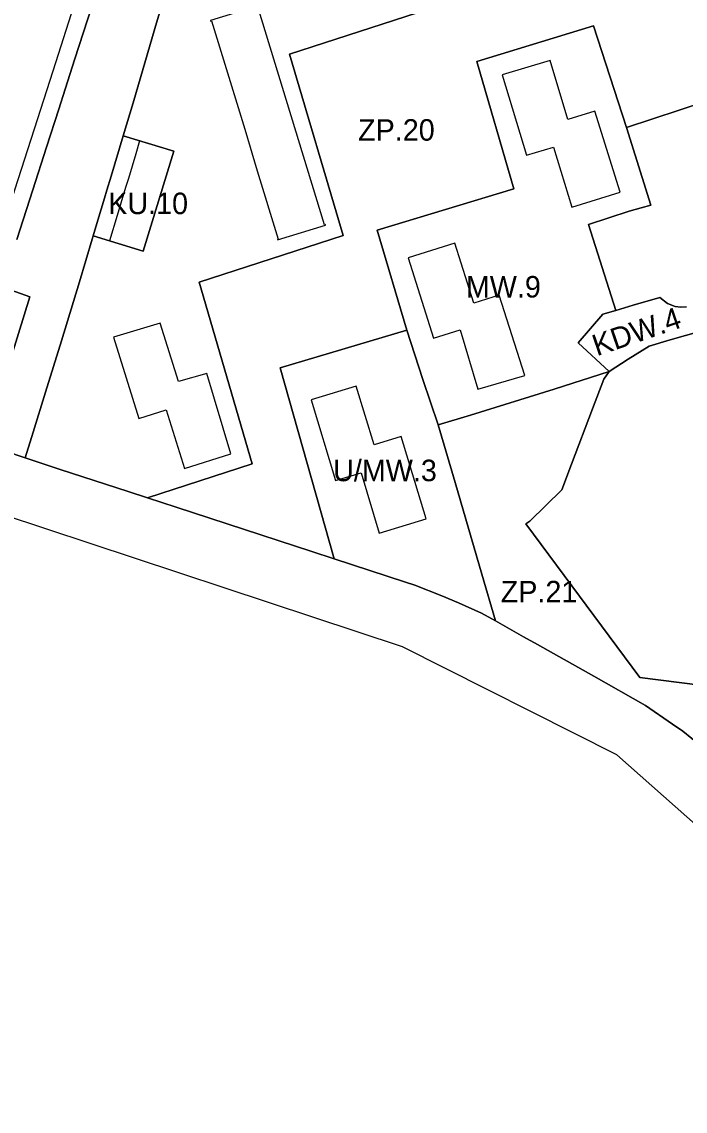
# Model space of a CAD drawing. Extents: x 7429178 to 7430831, y 5550228 to 5551611.
# Drawn here: x 7430171.5 to 7430325.9, y 5550756.2 to 5551009.6 of the extents above; entities that cross this region are included whole.
import ezdxf

# ---------------------------------------------------------------- set-up
doc = ezdxf.new("R2010")
doc.units = 0
for name, color, linetype in [('linie rozgraniczające', 7, 'Continuous'), ('nieprzekraczalne linie zabudowy', 7, 'Continuous'), ('obowiazujace linie zabudowy', 7, 'Continuous'), ('przeznaczenia terenów', 7, 'Continuous')]:
    doc.layers.add(name, color=color, linetype=linetype)

msp = doc.modelspace()

# ---------------------------------------------------------------- linework, layer by layer
at = {"layer": 'linie rozgraniczające'}
for points in [[(7430170.65, 5551043.22), (7430177.48, 5551062.44), (7430199.45, 5551057.06), (7430199.45, 5551057.06), (7430199.42, 5551056.95), (7430199.42, 5551056.95), (7430199.35, 5551056.75), (7430199.26, 5551056.46), (7430199.31, 5551056.2), (7430199.96, 5551050.84), (7430199.96, 5551050.84), (7430198.56, 5551046.5), (7430195.75, 5551037.8), (7430192.64, 5551028.18), (7430187.78, 5551013.14), (7430183.84, 5551000.93), (7430181.57, 5550993.91), (7430180.06, 5550989.22), (7430177.24, 5550980.42), (7430174.04, 5550970.46), (7430170.35, 5550958.95)], [(7430205.83, 5551019.51), (7430202.46, 5551008.03), (7430197.37, 5550990.71), (7430195.07, 5550983.04), (7430192.26, 5550973.68), (7430191.28, 5550970.4), (7430190.71, 5550968.51), (7430189.18, 5550963.43), (7430188.08, 5550959.77), (7430187.84, 5550958.98), (7430184.88, 5550949.09), (7430180.7, 5550935.39), (7430177, 5550923.42), (7430174.12, 5550914.11), (7430172.28, 5550908.16), (7430162.79, 5550911.32)], [(7430271.64, 5551014.25), (7430233.79, 5551002.02), (7430246.24, 5550959.84), (7430212.78, 5550949.01), (7430225.12, 5550906.71), (7430200.69, 5550898.84), (7430196.19, 5550900.31), (7430180.41, 5550905.46), (7430172.28, 5550908.16), (7430174.12, 5550914.11), (7430177, 5550923.42), (7430180.7, 5550935.39), (7430184.88, 5550949.09), (7430187.84, 5550958.98), (7430188.08, 5550959.77), (7430199.73, 5550956.21), (7430206.83, 5550979.45), (7430195.07, 5550983.04), (7430197.37, 5550990.71), (7430202.46, 5551008.03), (7430205.83, 5551019.51)], [(7430348.95, 5550997.08), (7430312.19, 5550985), (7430304.56, 5551008.63), (7430277.37, 5551000.36), (7430285.99, 5550970.73), (7430254.2, 5550961.12), (7430261.07, 5550937.83), (7430231.57, 5550929.08), (7430244.2, 5550884.65), (7430238.98, 5550886.35), (7430207.37, 5550896.66), (7430200.69, 5550898.84), (7430225.12, 5550906.71), (7430212.78, 5550949.01), (7430246.24, 5550959.84), (7430233.79, 5551002.02), (7430271.64, 5551014.25)], [(7430170.35, 5550958.95), (7430174.04, 5550970.46), (7430177.24, 5550980.42), (7430180.06, 5550989.22), (7430181.57, 5550993.91), (7430183.84, 5551000.93), (7430187.78, 5551013.14)], [(7430326.2, 5550943.27), (7430324.88, 5550943.21), (7430323.51, 5550943.37), (7430321.77, 5550944.04), (7430319.98, 5550945.46), (7430313.78, 5550943.63), (7430309.71, 5550942.43), (7430303.33, 5550962.38), (7430312.79, 5550965.49), (7430315.62, 5550966.32), (7430317.83, 5550966.94), (7430312.19, 5550985), (7430348.95, 5550997.08)], [(7430166.8, 5550947.9), (7430173.35, 5550945.62), (7430173.35, 5550945.62), (7430167.77, 5550927.5)], [(7430167.77, 5550927.5), (7430173.35, 5550945.62), (7430166.8, 5550947.9)], [(7430333.6, 5550938.76), (7430322.34, 5550935.57), (7430317.48, 5550934.13), (7430312.61, 5550931.06), (7430308.18, 5550928.25), (7430300.93, 5550934.9), (7430306.73, 5550941.55), (7430309.71, 5550942.43), (7430313.78, 5550943.63), (7430319.98, 5550945.46), (7430321.77, 5550944.04), (7430323.51, 5550943.37), (7430324.88, 5550943.21), (7430326.2, 5550943.27)], [(7430339.11, 5550854.01), (7430315.27, 5550857.02), (7430288.75, 5550892.75), (7430289.71, 5550893.37), (7430297.12, 5550900.68), (7430299.4, 5550906.67), (7430304.3, 5550919.54), (7430306.93, 5550926.44), (7430308.17, 5550928.24), (7430308.18, 5550928.25), (7430312.61, 5550931.06), (7430317.48, 5550934.13), (7430322.34, 5550935.57), (7430333.6, 5550938.76)], [(7430329.47, 5550841.17), (7430325.35, 5550844.54), (7430322.94, 5550846.2), (7430316.66, 5550850.54), (7430304.61, 5550857.32), (7430291.49, 5550864.69), (7430288.27, 5550866.5), (7430281.69, 5550870.2), (7430278.54, 5550881.07), (7430272.31, 5550902.38), (7430268.34, 5550915.78), (7430275.9, 5550918.1), (7430295.37, 5550924.11), (7430308.17, 5550928.24), (7430306.93, 5550926.44), (7430304.3, 5550919.54), (7430299.4, 5550906.67), (7430297.12, 5550900.68), (7430289.71, 5550893.37), (7430288.75, 5550892.75), (7430315.27, 5550857.02), (7430339.11, 5550854.01)], [(7430162.79, 5550911.32), (7430172.28, 5550908.16), (7430180.41, 5550905.46), (7430196.19, 5550900.31), (7430200.69, 5550898.84), (7430207.37, 5550896.66), (7430238.98, 5550886.35), (7430244.2, 5550884.65), (7430260.74, 5550879.25), (7430262.98, 5550878.52), (7430269.25, 5550876.04), (7430273.08, 5550874.43), (7430278.42, 5550872.04), (7430281.69, 5550870.2), (7430288.27, 5550866.5), (7430291.49, 5550864.69), (7430304.61, 5550857.32), (7430316.66, 5550850.54), (7430322.94, 5550846.2), (7430325.35, 5550844.54), (7430329.47, 5550841.17)], [(7430385.48, 5550754.46), (7430377.38, 5550769.13), (7430347.27, 5550805.99), (7430309.96, 5550839.07), (7430260.09, 5550864.18), (7430166.77, 5550895.04)]]:
    msp.add_lwpolyline(points, dxfattribs=at)
for points in [[(7430312.19, 5550985), (7430317.83, 5550966.94), (7430315.62, 5550966.32), (7430312.79, 5550965.49), (7430303.33, 5550962.38), (7430309.71, 5550942.43), (7430306.73, 5550941.55), (7430300.93, 5550934.9), (7430308.18, 5550928.25), (7430308.17, 5550928.24), (7430295.37, 5550924.11), (7430275.9, 5550918.1), (7430268.34, 5550915.78), (7430264.84, 5550926.36), (7430261.07, 5550937.83), (7430254.2, 5550961.12), (7430285.99, 5550970.73), (7430277.37, 5551000.36), (7430304.56, 5551008.63)], [(7430206.83, 5550979.45), (7430199.73, 5550956.21), (7430188.08, 5550959.77), (7430189.18, 5550963.43), (7430190.71, 5550968.51), (7430191.28, 5550970.4), (7430192.26, 5550973.68), (7430195.07, 5550983.04)], [(7430281.69, 5550870.2), (7430278.42, 5550872.04), (7430273.08, 5550874.43), (7430269.25, 5550876.04), (7430262.98, 5550878.52), (7430260.74, 5550879.25), (7430244.2, 5550884.65), (7430231.57, 5550929.08), (7430261.07, 5550937.83), (7430264.84, 5550926.36), (7430268.34, 5550915.78), (7430272.31, 5550902.38), (7430278.54, 5550881.07)]]:
    msp.add_lwpolyline(points, close=True, dxfattribs=at)
at = {"layer": 'nieprzekraczalne linie zabudowy'}
for points in [[(7430162.97, 5550949.06), (7430165.63, 5550957.33), (7430169.85, 5550970.48), (7430174.4, 5550984.68), (7430178.74, 5550998.18), (7430183.66, 5551013.4), (7430189.13, 5551030.33), (7430194.45, 5551046.81), (7430195.88, 5551051.23), (7430194.95, 5551058.17)], [(7430198.9, 5550981.89), (7430197.99, 5550978.85), (7430197.12, 5550976), (7430196.27, 5550973.12), (7430195.64, 5550971.04), (7430194.54, 5550967.36), (7430193.68, 5550964.5), (7430191.91, 5550958.62)]]:
    msp.add_lwpolyline(points, dxfattribs=at)
at = {"layer": 'obowiazujace linie zabudowy'}
for points in [[(7430242.18, 5550962.25), (7430242.13, 5550962.43), (7430241.91, 5550962.36), (7430226.4, 5551013.06), (7430226.63, 5551013.13), (7430226.59, 5551013.28), (7430215.35, 5551009.86), (7430215.4, 5551009.72), (7430215.61, 5551009.75), (7430223.37, 5550984.6), (7430226.26, 5550974.88), (7430231.17, 5550959.03), (7430230.95, 5550958.96), (7430230.99, 5550958.83), (7430242.18, 5550962.25)], [(7430283.28, 5550997.19), (7430288.96, 5550978.52), (7430295.25, 5550980.43), (7430299.5, 5550966.45), (7430310.7, 5550969.9), (7430304.82, 5550988.77), (7430298.56, 5550986.8), (7430294.45, 5551000.59), (7430283.28, 5550997.19)], [(7430288.57, 5550927.27), (7430282.6, 5550946.01), (7430276.7, 5550944.13), (7430272.25, 5550958.09), (7430261.37, 5550954.62), (7430267.31, 5550935.98), (7430273.46, 5550937.94), (7430277.64, 5550924.13), (7430288.57, 5550927.27)], [(7430198.72, 5550917.29), (7430205.05, 5550919.27), (7430209.32, 5550905.64), (7430220.15, 5550909.04), (7430214.53, 5550927.73), (7430207.92, 5550925.86), (7430203.71, 5550939.44), (7430192.8, 5550936.23), (7430198.72, 5550917.29)], [(7430265.57, 5550893.92), (7430259.79, 5550913.09), (7430253.45, 5550911.18), (7430249.25, 5550924.82), (7430238.79, 5550921.59), (7430244.45, 5550902.83), (7430250.44, 5550904.63), (7430254.66, 5550890.63), (7430265.57, 5550893.92)]]:
    msp.add_lwpolyline(points, dxfattribs=at)

# ---------------------------------------------------------------- texts
at = {"layer": 'przeznaczenia terenów'}
for s, p in [('ZP.20', (7430249.73, 5550981.91)), ('KU.10', (7430191.58, 5550964.82)), ('MW.9', (7430274.81, 5550945.43)), ('U/MW.3', (7430243.92, 5550902.7)), ('ZP.21', (7430282.93, 5550874.52))]:
    msp.add_text(s, height=5, dxfattribs=at).set_placement(p)
msp.add_text('KDW.4', height=5, rotation=18.8079, dxfattribs=at).set_placement((7430305.3, 5550931.73))

doc.saveas('drawing.dxf')
